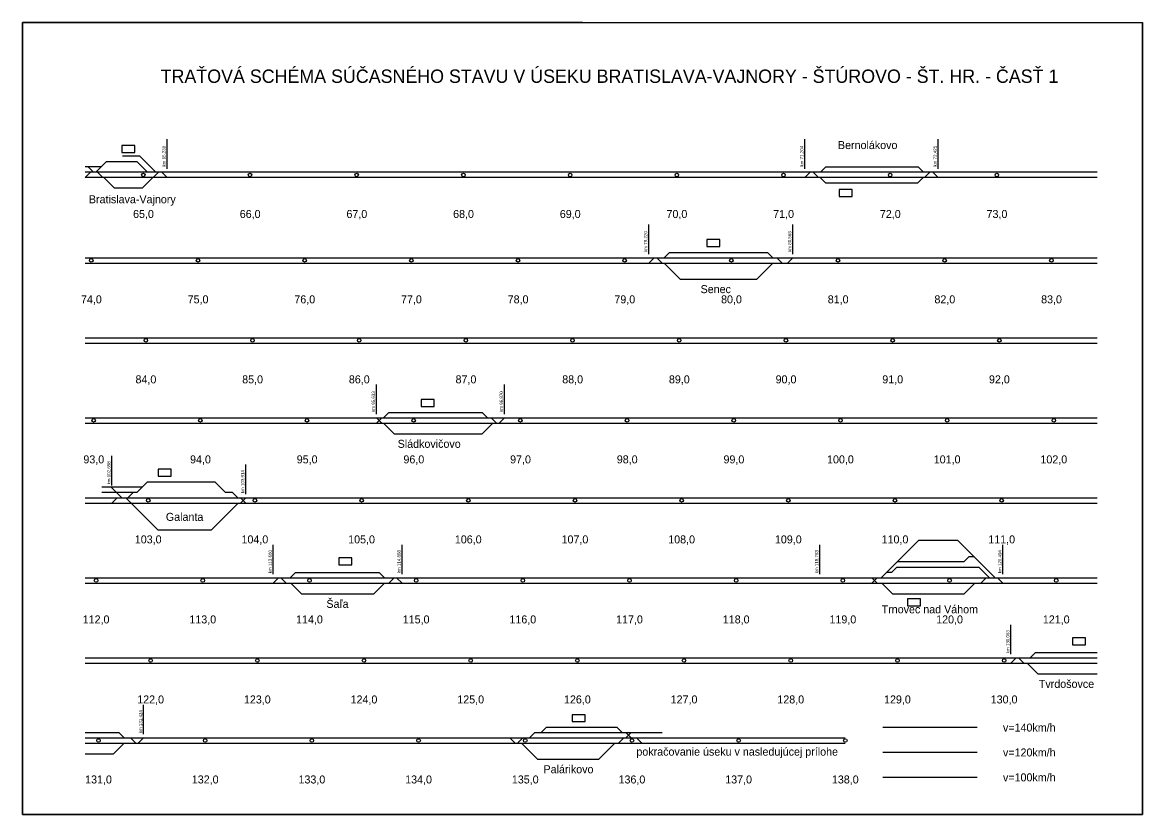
# Model space of a CAD drawing. Extents: x 44 to 1904, y 374 to 671.
# Drawn here: x 597.3 to 1017.3, y 373.6 to 670.6 of the extents above; entities that cross this region are included whole.
import ezdxf

# ---------------------------------------------------------------- set-up
doc = ezdxf.new("R2010")
doc.units = 0
for name, color, linetype in [('2', 7, 'Continuous'), ('NAVRH', 7, 'Continuous'), ('Vrstva 1', 7, 'Continuous')]:
    doc.layers.add(name, color=color, linetype=linetype)

msp = doc.modelspace()

# ---------------------------------------------------------------- linework, layer by layer
at = {"layer": '2'}
for p, q in [((628.8, 618.39), (640.22, 618.39)), ((641.36, 620.39), (634.84, 620.39)), ((626.8, 616.39), (620.78, 616.39)), ((898.51, 616.39), (933.12, 616.39)), ((898.43, 610.39), (933.07, 610.39)), ((839.96, 584.39), (876.68, 584.39)), ((620.78, 582.39), (832.11, 582.39)), ((620.78, 580.39), (832.11, 580.39)), ((832.11, 582.39), (886.11, 582.39)), ((832.11, 580.39), (886.11, 580.39)), ((886.11, 582.39), (1000.32, 582.39)), ((886.11, 580.39), (1000.32, 580.39)), ((843.89, 574.39), (872.63, 574.39)), ((620.78, 552.39), (1000.32, 552.39)), ((620.78, 550.39), (1000.32, 550.39)), ((620.78, 522.39), (650.6, 522.39)), ((620.78, 522.39), (730.01, 522.39)), ((730.01, 522.39), (778.01, 522.39)), ((734.73, 524.39), (769.72, 524.39)), ((778.01, 522.39), (1000.32, 522.39)), ((620.78, 520.39), (649.52, 520.39)), ((620.78, 520.39), (730.01, 520.39)), ((730.01, 520.39), (778.01, 520.39)), ((778.01, 520.39), (1000.32, 520.39)), ((736.66, 516.39), (769.69, 516.39)), ((642.24, 496.39), (627.02, 496.39)), ((644.24, 498.39), (669.4, 498.39)), ((620.78, 492.39), (630.83, 492.39)), ((640.24, 494.39), (627.02, 494.39)), ((630.83, 492.39), (681.03, 492.39)), ((676.13, 494.39), (673.4, 494.39)), ((681.03, 492.39), (1000.32, 492.39)), ((620.78, 490.39), (630.83, 490.39)), ((630.83, 490.39), (681.03, 490.39)), ((681.03, 490.39), (1000.32, 490.39)), ((648.07, 480.39), (668.22, 480.39)), ((947.98, 476.39), (933.3, 476.39)), ((925.13, 466.39), (955.87, 466.39)), ((950.23, 468.39), (925.3, 468.39)), ((952.23, 470.39), (953.98, 470.39)), ((620.78, 462.39), (691.32, 462.39)), ((691.32, 462.39), (739.62, 462.39)), ((699.73, 464.39), (731, 464.39)), ((739.62, 462.39), (896.24, 462.39)), ((896.24, 462.39), (964.92, 462.39)), ((923.13, 464.39), (921.3, 464.39)), ((964.92, 462.39), (1000.32, 462.39)), ((620.78, 460.39), (691.32, 460.39)), ((691.32, 460.39), (739.62, 460.39)), ((739.62, 460.39), (896.24, 460.39)), ((896.24, 460.39), (964.92, 460.39)), ((964.92, 460.39), (1000.32, 460.39)), ((701.93, 456.39), (729, 456.39)), ((923.5, 456.39), (950.45, 456.39)), ((977.14, 434.39), (1000.32, 434.39)), ((620.78, 432.39), (967.9, 432.39)), ((620.78, 430.39), (967.9, 430.39)), ((967.9, 432.39), (1000.32, 432.39)), ((967.9, 430.39), (1000.32, 430.39)), ((977.97, 426.39), (1000.32, 426.39)), ((620.78, 404.39), (633.46, 404.39)), ((789.39, 404.39), (791.77, 404.39)), ((791.77, 404.39), (837.2, 404.39)), ((793.77, 406.39), (820.23, 406.39)), ((620.78, 402.39), (642.75, 402.39)), ((620.78, 400.39), (642.75, 400.39)), ((642.75, 402.39), (905.83, 402.39)), ((642.75, 400.39), (905.83, 400.39)), ((620.78, 396.39), (631.46, 396.39)), ((790.47, 394.39), (813.42, 394.39))]:
    msp.add_line(p, q, dxfattribs=at)
at = {"layer": 'NAVRH'}
for p, q in [((626.8, 616.39), (628.8, 618.39)), ((642.22, 616.39), (640.22, 618.39)), ((643.36, 618.39), (641.36, 620.39)), ((645.36, 616.39), (643.36, 618.39)), ((620.78, 612.39), (622.78, 614.39)), ((623.99, 614.39), (621.99, 616.39)), ((624.8, 614.39), (626.8, 616.39)), ((627.51, 612.39), (625.51, 614.39)), ((644.22, 614.39), (642.22, 616.39)), ((647.36, 614.39), (645.36, 616.39)), ((646.31, 612.39), (648.31, 614.39)), ((651.53, 612.39), (649.53, 614.39)), ((890.65, 612.39), (892.65, 614.39)), ((895.75, 612.39), (893.75, 614.39)), ((896.51, 614.39), (898.51, 616.39)), ((935.12, 614.39), (933.12, 616.39)), ((935.55, 612.39), (937.55, 614.39)), ((940.65, 612.39), (938.65, 614.39)), ((629.86, 610.39), (627.86, 612.39)), ((631.86, 608.39), (629.86, 610.39)), ((642.18, 608.39), (644.18, 610.39)), ((644.18, 610.39), (646.18, 612.39)), ((898.43, 610.39), (896.43, 612.39)), ((933.07, 610.39), (935.07, 612.39)), ((837.96, 582.39), (839.96, 584.39)), ((878.68, 582.39), (876.68, 584.39)), ((832.11, 580.39), (834.11, 582.39)), ((837.21, 580.39), (835.21, 582.39)), ((839.89, 578.39), (837.89, 580.39)), ((876.63, 578.39), (878.63, 580.39)), ((882.22, 580.39), (880.22, 582.39)), ((884.11, 580.39), (886.11, 582.39)), ((841.89, 576.39), (839.89, 578.39)), ((843.89, 574.39), (841.89, 576.39)), ((872.63, 574.39), (874.63, 576.39)), ((874.63, 576.39), (876.63, 578.39)), ((730.01, 520.39), (732.01, 522.39)), ((732.01, 520.39), (730.01, 522.39)), ((732.73, 522.39), (734.73, 524.39)), ((771.72, 522.39), (769.72, 524.39)), ((775.1, 520.39), (773.1, 522.39)), ((776.01, 520.39), (778.01, 522.39)), ((734.66, 518.39), (732.66, 520.39)), ((736.66, 516.39), (734.66, 518.39)), ((769.69, 516.39), (771.69, 518.39)), ((771.69, 518.39), (773.69, 520.39)), ((632.53, 494.39), (630.53, 496.39)), ((640.24, 494.39), (642.24, 496.39)), ((642.24, 496.39), (644.24, 498.39)), ((671.4, 496.39), (669.4, 498.39)), ((673.4, 494.39), (671.4, 496.39)), ((630.83, 490.39), (632.83, 492.39)), ((634.53, 492.39), (632.53, 494.39)), ((638.07, 490.39), (636.07, 492.39)), ((636.83, 492.39), (638.83, 494.39)), ((678.13, 492.39), (676.13, 494.39)), ((681.03, 490.39), (679.03, 492.39)), ((679.03, 490.39), (681.03, 492.39)), ((640.07, 488.39), (638.07, 490.39)), ((642.07, 486.39), (640.07, 488.39)), ((674.22, 486.39), (676.22, 488.39)), ((676.22, 488.39), (678.22, 490.39)), ((644.07, 484.39), (642.07, 486.39)), ((646.07, 482.39), (644.07, 484.39)), ((670.22, 482.39), (672.22, 484.39)), ((672.22, 484.39), (674.22, 486.39)), ((648.07, 480.39), (646.07, 482.39)), ((668.22, 480.39), (670.22, 482.39)), ((925.3, 468.39), (933.3, 476.39)), ((949.98, 474.39), (947.98, 476.39)), ((951.98, 472.39), (949.98, 474.39)), ((953.98, 470.39), (951.98, 472.39)), ((921.3, 464.39), (923.3, 466.39)), ((923.13, 464.39), (925.13, 466.39)), ((923.3, 466.39), (925.3, 468.39)), ((950.23, 468.39), (952.23, 470.39)), ((955.98, 468.39), (953.98, 470.39)), ((957.87, 464.39), (955.87, 466.39)), ((957.98, 466.39), (955.98, 468.39)), ((959.98, 464.39), (957.98, 466.39)), ((691.32, 460.39), (693.32, 462.39)), ((696.23, 460.39), (694.23, 462.39)), ((697.73, 462.39), (699.73, 464.39)), ((733, 462.39), (731, 464.39)), ((734.71, 460.39), (736.71, 462.39)), ((739.62, 460.39), (737.62, 462.39)), ((917.8, 460.39), (915.8, 462.39)), ((915.8, 460.39), (917.8, 462.39)), ((919.3, 462.39), (921.3, 464.39)), ((956.6, 460.39), (958.6, 462.39)), ((959.87, 462.39), (957.87, 464.39)), ((961.98, 462.39), (959.98, 464.39)), ((964.92, 460.39), (962.92, 462.39)), ((699.93, 458.39), (697.93, 460.39)), ((701.93, 456.39), (699.93, 458.39)), ((729, 456.39), (733, 460.39)), ((921.5, 458.39), (919.5, 460.39)), ((923.5, 456.39), (921.5, 458.39)), ((950.45, 456.39), (952.45, 458.39)), ((952.45, 458.39), (954.45, 460.39)), ((975.14, 432.39), (977.14, 434.39)), ((967.9, 430.39), (969.9, 432.39)), ((972.8, 430.39), (970.8, 432.39)), ((975.97, 428.39), (973.97, 430.39)), ((977.97, 426.39), (975.97, 428.39)), ((635.46, 402.39), (633.46, 404.39)), ((787.39, 402.39), (789.39, 404.39)), ((791.77, 404.39), (793.77, 406.39)), ((822.23, 404.39), (820.23, 406.39)), ((825.56, 402.39), (823.56, 404.39)), ((823.56, 402.39), (825.56, 404.39)), ((633.46, 398.39), (635.46, 400.39)), ((639.84, 400.39), (637.84, 402.39)), ((640.75, 400.39), (642.75, 402.39)), ((782.07, 400.39), (780.07, 402.39)), ((782.98, 400.39), (784.98, 402.39)), ((786.47, 398.39), (784.47, 400.39)), ((817.42, 398.39), (819.42, 400.39)), ((820.75, 400.39), (822.75, 402.39)), ((829.49, 400.39), (827.49, 402.39)), ((631.46, 396.39), (633.46, 398.39)), ((788.47, 396.39), (786.47, 398.39)), ((790.47, 394.39), (788.47, 396.39)), ((813.42, 394.39), (815.42, 396.39)), ((815.42, 396.39), (817.42, 398.39))]:
    msp.add_line(p, q, dxfattribs=at)
for points in [[(634.54, 621.79), (639.43, 621.79), (639.43, 624.39), (634.54, 624.39)], [(903.51, 605.31), (908.41, 605.31), (908.41, 607.91), (903.51, 607.91)], [(853.86, 586.63), (858.75, 586.63), (858.75, 589.23), (853.86, 589.23)], [(746.84, 526.63), (751.74, 526.63), (751.74, 529.23), (746.84, 529.23)], [(648.21, 500.53), (653.11, 500.53), (653.11, 503.13), (648.21, 503.13)], [(715.93, 467.25), (720.82, 467.25), (720.82, 469.86), (715.93, 469.86)], [(929.11, 451.91), (934, 451.91), (934, 454.51), (929.11, 454.51)], [(990.99, 437.27), (995.88, 437.27), (995.88, 439.87), (990.99, 439.87)], [(803.44, 408.45), (808.33, 408.45), (808.33, 411.05), (803.44, 411.05)]]:
    msp.add_lwpolyline(points, close=True, dxfattribs=at)
for centre in [(642.65, 613.39), (682.65, 613.39), (722.65, 613.39), (762.65, 613.39), (802.65, 613.39), (842.65, 613.39), (882.65, 613.39), (922.65, 613.39), (962.65, 613.39), (623.11, 581.39), (663.11, 581.39), (703.11, 581.39), (743.11, 581.39), (783.11, 581.39), (823.11, 581.39), (863.11, 581.39), (903.11, 581.39), (943.11, 581.39), (983.11, 581.39), (643.56, 551.39), (683.56, 551.39), (723.56, 551.39), (763.56, 551.39), (803.56, 551.39), (843.56, 551.39), (883.56, 551.39), (923.56, 551.39), (963.56, 551.39), (624.01, 521.39), (664.01, 521.39), (704.01, 521.39), (744.01, 521.39), (784.01, 521.39), (824.01, 521.39), (864.01, 521.39), (904.01, 521.39), (944.01, 521.39), (984.01, 521.39), (644.47, 491.39), (684.47, 491.39), (724.47, 491.39), (764.47, 491.39), (804.47, 491.39), (844.47, 491.39), (884.47, 491.39), (924.47, 491.39), (964.47, 491.39), (624.92, 461.39), (664.92, 461.39), (704.92, 461.39), (744.92, 461.39), (784.92, 461.39), (824.92, 461.39), (864.92, 461.39), (904.92, 461.39), (944.92, 461.39), (984.92, 461.39), (645.38, 431.39), (685.38, 431.39), (725.38, 431.39), (765.38, 431.39), (805.38, 431.39), (845.38, 431.39), (885.38, 431.39), (925.38, 431.39), (965.38, 431.39), (625.83, 401.39), (665.83, 401.39), (705.83, 401.39), (745.83, 401.39), (785.83, 401.39), (825.83, 401.39), (865.83, 401.39), (905.83, 401.39)]:
    msp.add_circle(centre, 0.666, dxfattribs=at)
at = {"layer": 'Vrstva 1'}
for p, q in [((807.3, 670.6), (597.3, 670.6)), ((597.3, 670.6), (597.3, 373.6)), ((807.3, 670.6), (1017.3, 670.6)), ((1017.3, 373.6), (1017.3, 670.6)), ((651.53, 615.71), (651.53, 626.79)), ((890.65, 615.71), (890.65, 626.79)), ((940.65, 615.71), (940.65, 626.79)), ((651.53, 614.39), (620.78, 614.39)), ((686.65, 614.39), (651.53, 614.39)), ((890.65, 614.39), (686.65, 614.39)), ((913.53, 614.39), (890.65, 614.39)), ((940.65, 614.39), (913.53, 614.39)), ((1000.32, 614.39), (940.65, 614.39)), ((651.53, 612.39), (620.78, 612.39)), ((688.82, 612.39), (651.53, 612.39)), ((890.65, 612.39), (688.82, 612.39)), ((913.53, 612.39), (890.65, 612.39)), ((940.65, 612.39), (913.53, 612.39)), ((1000.32, 612.39), (940.65, 612.39)), ((642.18, 608.39), (631.86, 608.39)), ((832.11, 583.71), (832.11, 594.79)), ((886.11, 583.71), (886.11, 594.79)), ((730.01, 523.71), (730.01, 534.79)), ((778.01, 523.71), (778.01, 534.79)), ((630.83, 496.98), (630.83, 508.06)), ((681.03, 493.71), (681.03, 504.79)), ((691.32, 463.71), (691.32, 474.79)), ((739.62, 463.71), (739.62, 474.79)), ((896.24, 463.71), (896.24, 474.79)), ((964.92, 463.71), (964.92, 474.79)), ((967.9, 433.71), (967.9, 444.79)), ((642.75, 403.71), (642.75, 414.79)), ((955.21, 406.23), (919.96, 406.23)), ((955.21, 396.89), (919.96, 396.89)), ((955.21, 387.55), (919.96, 387.55)), ((597.3, 373.6), (807.3, 373.6)), ((807.3, 373.6), (1017.3, 373.6))]:
    msp.add_line(p, q, dxfattribs=at)
msp.add_lwpolyline([(597.3, 670.6), (1017.3, 670.6), (1017.3, 373.6), (597.3, 373.6)], close=True, dxfattribs=at)

# ---------------------------------------------------------------- texts
at = {"layer": 'NAVRH'}
for s, height, p in [('TRAŤOVÁ SCHÉMA SÚČASNÉHO STAVU V ÚSEKU BRATISLAVA-VAJNORY - ŠTÚROVO - ŠT. HR. - ČASŤ 1 ', 5, (649.13, 647.93)), ('Bernolákovo', 3, (903.07, 623.11)), ('Senec', 3, (851.57, 569.1)), ('75,0', 3, (659.25, 565.27)), ('76,0', 3, (699.25, 565.27)), ('77,0', 3, (739.25, 565.27)), ('78,0', 3, (779.25, 565.27)), ('79,0', 3, (819.25, 565.27)), ('80,0', 3, (859.25, 565.27)), ('81,0', 3, (899.25, 565.27)), ('82,0', 3, (939.25, 565.27)), ('83,0', 3, (979.25, 565.27)), ('84,0', 3, (639.7, 535.27)), ('85,0', 3, (679.7, 535.27)), ('86,0', 3, (719.7, 535.27)), ('87,0', 3, (759.7, 535.27)), ('88,0', 3, (799.7, 535.27)), ('89,0', 3, (839.7, 535.27)), ('90,0', 3, (879.7, 535.27)), ('91,0', 3, (919.7, 535.27)), ('92,0', 3, (959.7, 535.27)), ('Sládkovičovo', 3, (737.99, 511.1)), ('93,0', 3, (620.16, 505.27)), ('94,0', 3, (660.16, 505.27)), ('95,0', 3, (700.16, 505.27)), ('96,0', 3, (740.16, 505.27)), ('97,0', 3, (780.16, 505.27)), ('98,0', 3, (820.16, 505.27)), ('99,0', 3, (860.16, 505.27)), ('100,0', 3, (898.99, 505.27)), ('101,0', 3, (938.99, 505.27)), ('102,0', 3, (978.99, 505.27)), ('Galanta', 3, (651.09, 483.72)), ('103,0', 3, (639.44, 475.27)), ('104,0', 3, (679.44, 475.27)), ('105,0', 3, (719.44, 475.27)), ('106,0', 3, (759.44, 475.27)), ('107,0', 3, (799.44, 475.27)), ('108,0', 3, (839.44, 475.27)), ('109,0', 3, (879.44, 475.27)), ('110,0', 3, (919.44, 475.27)), ('111,0', 3, (959.44, 475.27)), ('Šaľa', 3, (711.29, 451.1)), ('113,0', 3, (659.9, 445.27)), ('114,0', 3, (699.9, 445.27)), ('115,0', 3, (739.9, 445.27)), ('116,0', 3, (779.9, 445.27)), ('117,0', 3, (819.9, 445.27)), ('118,0', 3, (859.9, 445.27)), ('119,0', 3, (899.9, 445.27)), ('120,0', 3, (939.9, 445.27)), ('121,0', 3, (979.9, 445.27)), ('122,0', 3, (640.35, 415.27)), ('123,0', 3, (680.35, 415.27)), ('124,0', 3, (720.35, 415.27)), ('125,0', 3, (760.35, 415.27)), ('126,0', 3, (800.35, 415.27)), ('127,0', 3, (840.35, 415.27)), ('128,0', 3, (880.35, 415.27)), ('129,0', 3, (920.35, 415.27)), ('130,0', 3, (960.35, 415.27)), ('pokračovanie úseku v nasledujúcej prílohe', 3, (827.5, 395.7)), ('131,0', 3, (620.81, 385.27)), ('132,0', 3, (660.81, 385.27)), ('133,0', 3, (700.81, 385.27)), ('134,0', 3, (740.81, 385.27)), ('135,0', 3, (780.81, 385.27)), ('136,0', 3, (820.81, 385.27)), ('137,0', 3, (860.81, 385.27)), ('138,0', 3, (900.81, 385.27))]:
    msp.add_text(s, height=height, dxfattribs=at).set_placement(p)
for s, p in [('Bratislava-Vajnory', (622.23, 602.79)), ('65,0', (638.79, 597.27)), ('66,0', (678.79, 597.27)), ('67,0', (718.79, 597.27)), ('68,0', (758.79, 597.27)), ('69,0', (798.79, 597.27)), ('70,0', (838.79, 597.27)), ('71,0', (878.79, 597.27)), ('72,0', (918.79, 597.27)), ('73,0', (958.79, 597.27)), ('74,0', (619.25, 565.27)), ('Trnovec nad Váhom', (919.46, 449.07)), ('112,0', (619.9, 445.27)), ('Tvrdošovce', (978.4, 421.1)), ('v=140km/h', (964.95, 404.73)), ('v=120km/h', (964.95, 395.39)), ('Palárikovo', (792.68, 389.1)), ('v=100km/h', (964.95, 386.05))]:
    msp.add_text(s, height=3, rotation=360, dxfattribs=at).set_placement(p)
at = {"layer": 'Vrstva 1'}
for s, p in [('km 65,230', (650.97, 616.57)), ('km 71,204', (890.1, 616.57)), ('km 72,425', (940.1, 616.57)), ('km 79,220', (831.55, 584.57)), ('km 80,568', (885.55, 584.57)), ('km 95,633', (729.46, 524.57)), ('km 96,870', (777.46, 524.57)), ('km 102,658', (630.28, 497.38)), ('km 103,914', (680.48, 494.11)), ('km 113,660', (690.77, 464.11)), ('km 114,868', (739.07, 464.1)), ('km 118,783', (895.69, 464.1)), ('km 120,494', (964.37, 464.11)), ('km 130,063', (967.34, 434.1)), ('km 131,424', (642.2, 404.11))]:
    msp.add_text(s, height=1.2, rotation=90, dxfattribs=at).set_placement(p)

doc.saveas('drawing.dxf')
